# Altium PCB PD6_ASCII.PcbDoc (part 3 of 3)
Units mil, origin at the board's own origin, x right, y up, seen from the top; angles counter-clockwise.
Board outline 8543.31 x 5314.96 mil, 4 copper layers (Top Layer, VBAT Plane, GND Plane, Bottom Layer), stack 62.8 mil thick; 258 components, 142 nets, 690 pads, 87 vias.
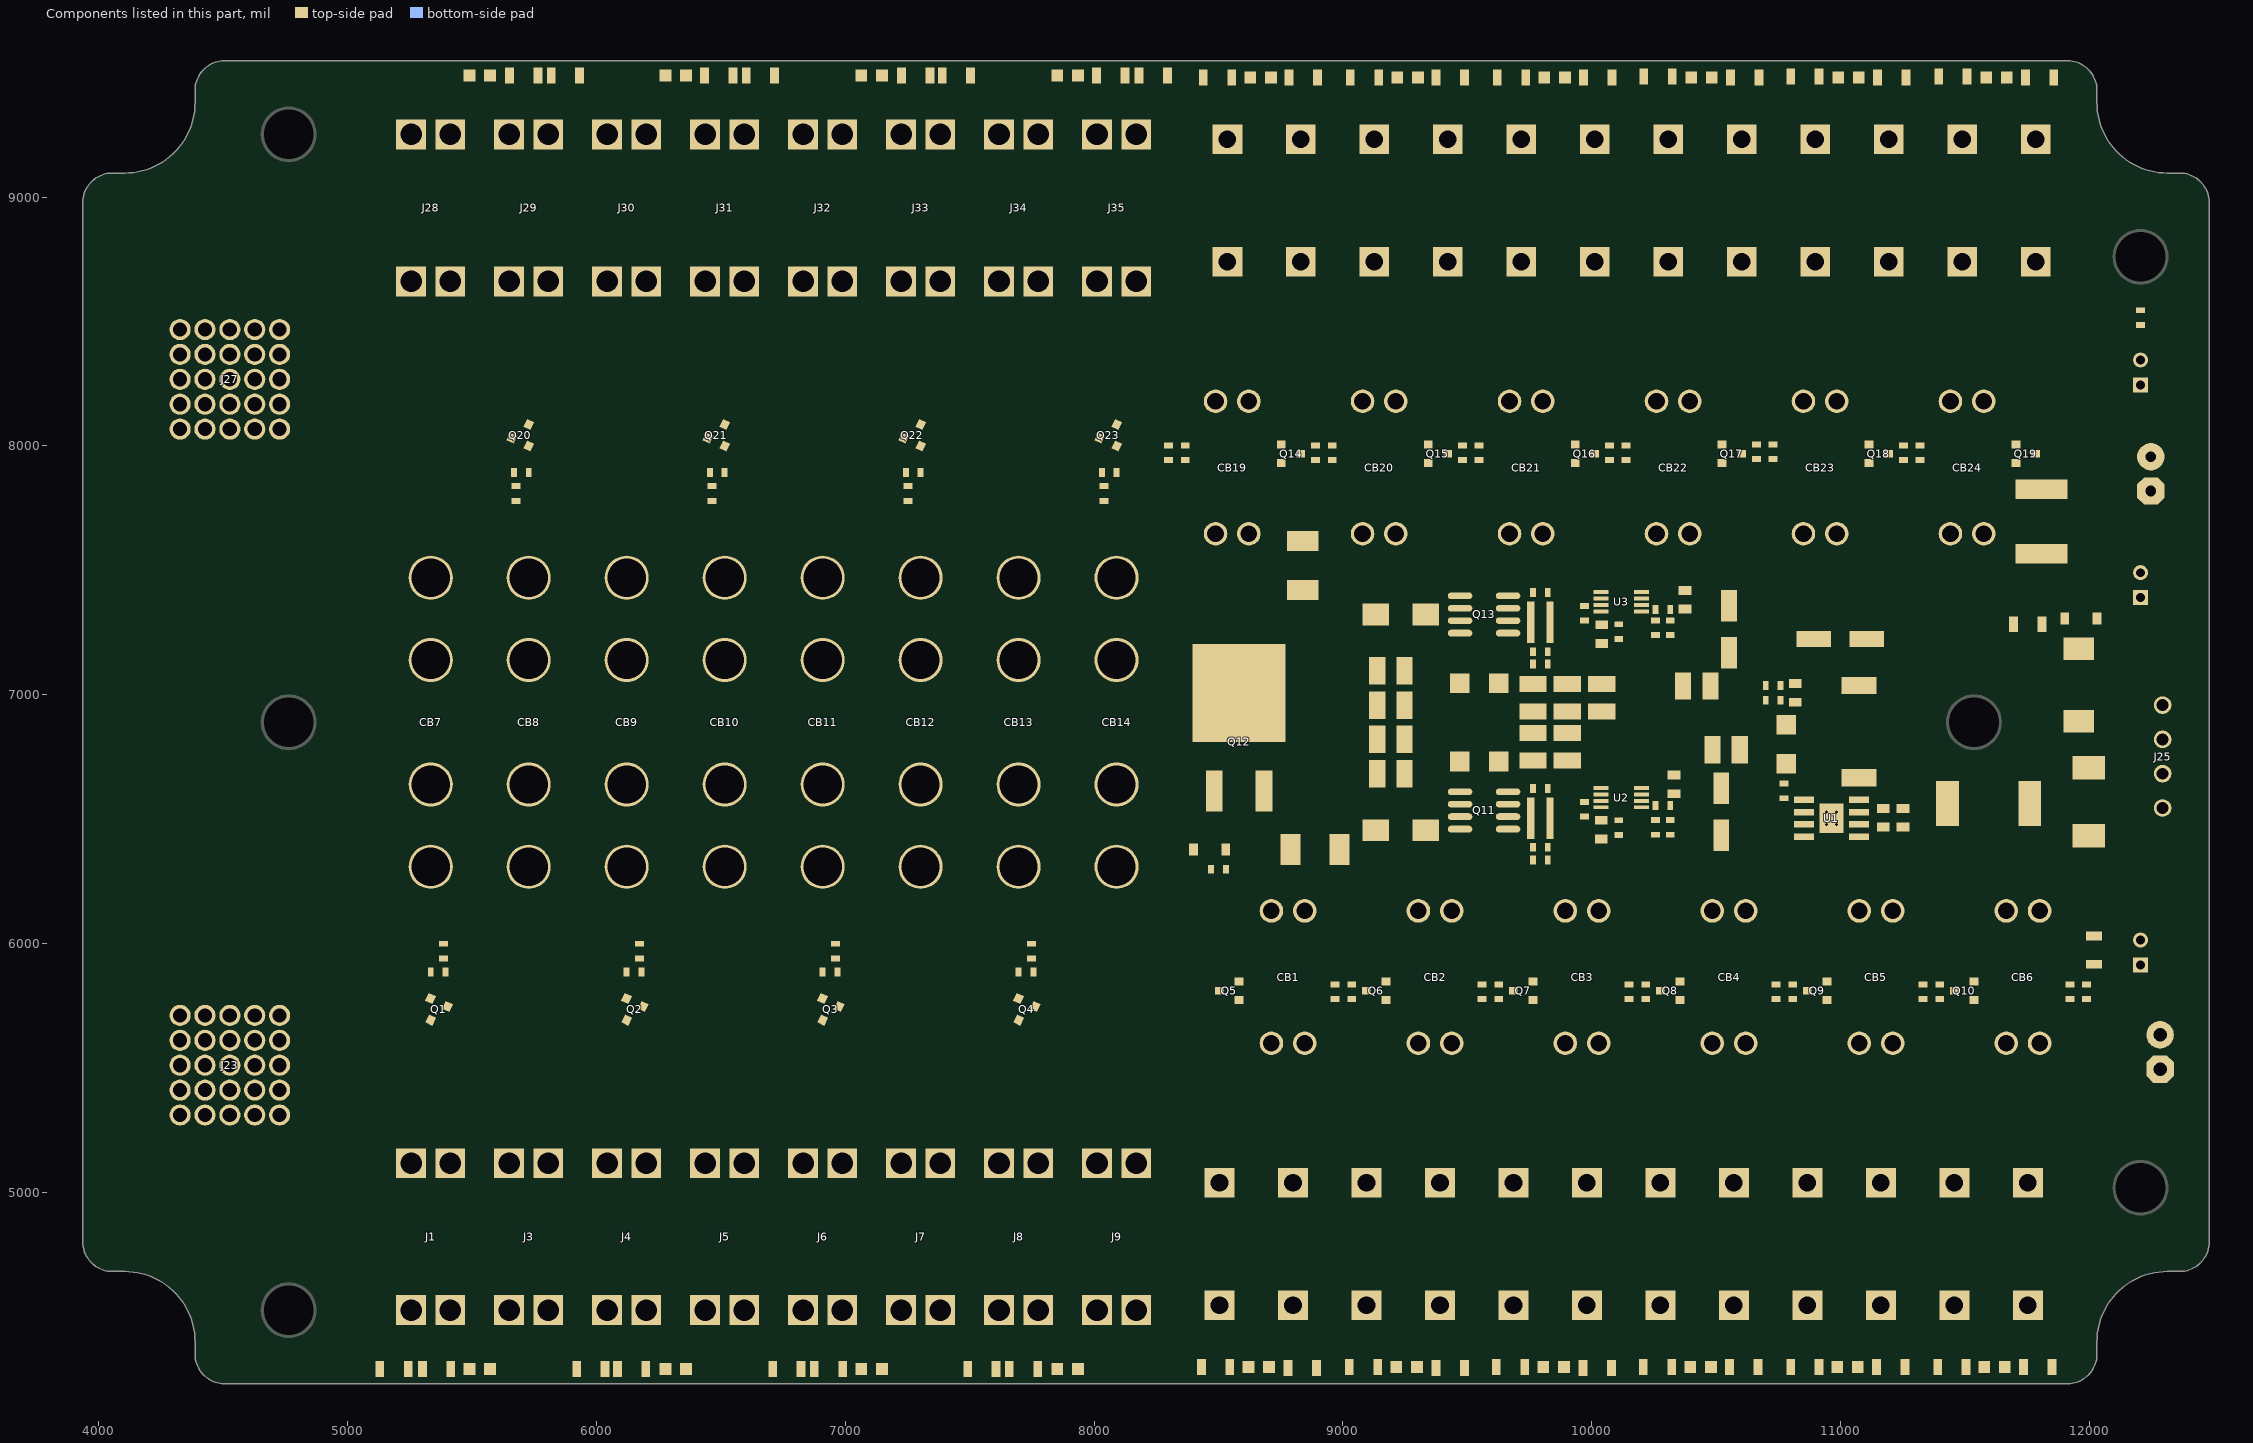
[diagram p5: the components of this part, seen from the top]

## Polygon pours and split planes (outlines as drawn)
VBAT on Top Layer "Top Layer-No Net" (solid, remove dead copper, pour order 1008): 8582.68,6259.84 11929.13,6259.84 11929.13,5870.08 8582.68,5870.08
VBAT on Top Layer "Top Layer-VBAT 1" (solid, remove dead copper, pour order 1007): 8257.87,7519.69 11669.29,7519.69 11669.29,7909.45 8257.87,7909.45 8257.87,7519.69
HIGHCURRENTOUT_3_2 on Top Layer "Top Layer-VBAT" (solid, remove dead copper, pour order 1020): 6338.58,7480.31 6338.58,7047.24 6299.21,7007.87 5944.88,7007.87 5905.51,7047.24 5905.51,7480.31 5748.03,7637.8 5748.03,8425.2 5905.51,8582.68 5905.51,9370.08 5944.88,9409.45 6299.21,9409.45 6338.58,9370.08 6338.58,8582.68 6496.06,8425.2 6496.06,7637.8
HIGHCURRENTOUT_2_2 on Top Layer "Top Layer-VBAT" (solid, remove dead copper, pour order 1019): 7125.98,7480.31 7125.98,7047.24 7086.61,7007.87 6732.28,7007.87 6692.91,7047.24 6692.91,7480.31 6535.43,7637.8 6535.43,8425.2 6692.91,8582.68 6692.91,9370.08 6732.28,9409.45 7086.61,9409.45 7125.98,9370.08 7125.98,8582.68 7283.46,8425.2 7283.46,7637.8
HIGHCURRENTOUT_1_2 on Top Layer "Top Layer-VBAT" (solid, remove dead copper, pour order 1018): 7913.39,7480.31 7913.39,7047.24 7874.02,7007.87 7519.69,7007.87 7480.31,7047.24 7480.31,7480.31 7322.83,7637.8 7322.83,8425.2 7480.31,8582.68 7480.31,9370.08 7519.69,9409.45 7874.02,9409.45 7913.39,9370.08 7913.39,8582.68 8070.87,8425.2 8070.87,7637.8
HIGHCURRENTOUT_4_2 on Top Layer "Top Layer-VBAT" (solid, remove dead copper, pour order 1014): 5551.18,7480.31 5551.18,7047.24 5511.81,7007.87 5157.48,7007.87 5118.11,7047.24 5118.11,7480.31 5039.37,7559.06 5039.37,8503.94 5118.11,8582.68 5118.11,9370.08 5157.48,9409.45 5511.81,9409.45 5551.18,9370.08 5551.18,8582.68 5708.66,8425.2 5708.66,7637.8
NetC3_2 on Top Layer "Top Layer-GND" (solid, remove dead copper, pour order 1000): 9566.93,6299.21 9734.25,6299.21 9734.25,6427.17 9812.99,6427.17 9812.99,6594.49 9606.3,6594.49 9566.93,6594.49
NetC19_2 on Top Layer "Top Layer-GND" (solid, remove dead copper, pour order 1002): 9566.93,7086.61 9734.25,7086.61 9734.25,7214.57 9812.99,7214.57 9812.99,7381.89 9606.3,7381.89 9566.93,7381.89
24_VIN on Top Layer "Top Layer-GND" (solid, remove dead copper, pour order 1001): 8858.27,7480.31 8858.27,6999.61 ccw(c8958.27,6999.61) 8958.27,6899.61 9183.07,6899.61 9183.07,7480.31
12_VIN on Top Layer "Top Layer-GND" (solid, remove dead copper, pour order 1003): 8858.27,6299.21 8858.27,6779.92 cw(c8958.27,6779.92) 8958.27,6879.92 9183.07,6879.92 9183.07,6299.21
HIGHCURRENTOUT_1_1 on Top Layer "Top Layer-VBAT" (solid, remove dead copper, pour order 1022): 5511.81,6299.21 5511.81,6732.28 5551.18,6771.65 5905.51,6771.65 5944.88,6732.28 5944.88,6299.21 6102.36,6141.73 6102.36,5354.33 5944.88,5196.85 5944.88,4409.45 5905.51,4370.08 5551.18,4370.08 5511.81,4409.45 5511.81,5196.85 5354.33,5354.33 5354.33,6141.73
HIGHCURRENTOUT_2_1 on Top Layer "Top Layer-VBAT" (solid, remove dead copper, pour order 1009): 6299.21,6299.21 6299.21,6732.28 6338.58,6771.65 6692.91,6771.65 6732.28,6732.28 6732.28,6299.21 6889.76,6141.73 6889.76,5354.33 6732.28,5196.85 6732.28,4409.45 6692.91,4370.08 6338.58,4370.08 6299.21,4409.45 6299.21,5196.85 6141.73,5354.33 6141.73,6141.73
HIGHCURRENTOUT_3_1 on Top Layer "Top Layer-VBAT" (solid, remove dead copper, pour order 1010): 7086.61,6299.21 7086.61,6732.28 7125.98,6771.65 7480.31,6771.65 7519.69,6732.28 7519.69,6299.21 7677.17,6141.73 7677.17,5354.33 7519.69,5196.85 7519.69,4409.45 7480.31,4370.08 7125.98,4370.08 7086.61,4409.45 7086.61,5196.85 6929.13,5354.33 6929.13,6141.73
HIGHCURRENTOUT_4_1 on Top Layer "Top Layer-VBAT" (solid, remove dead copper, pour order 1012): 7874.02,6299.21 7874.02,6732.28 7913.39,6771.65 8267.72,6771.65 8307.09,6732.28 8307.09,6299.21 8464.57,6141.73 8464.57,5354.33 8307.09,5196.85 8307.09,4409.45 8267.72,4370.08 7913.39,4370.08 7874.02,4409.45 7874.02,5196.85 7716.54,5354.33 7716.54,6141.73
VBAT on Top Layer "Top Layer-VBAT HP" (solid, remove dead copper, pour order 1023): 3838.58,7677.17 7913.39,7677.17 7913.39,7913.39 8257.87,7913.39 8257.87,6102.36 5511.81,6102.36 5511.81,4409.45 5000,4409.45 5000,4133.86 3838.58,4133.86
HIGHCURRENTOUT_2_1 on Bottom Layer "Top Layer-VBAT" (solid, remove dead copper, pour order 1004): 6299.21,6299.21 6299.21,6732.28 6338.58,6771.65 6692.91,6771.65 6732.28,6732.28 6732.28,6299.21 6889.76,6141.73 6889.76,5354.33 6732.28,5196.85 6732.28,5039.37 6692.91,5000 6338.58,5000 6299.21,5039.37 6299.21,5196.85 6141.73,5354.33 6141.73,6141.73
HIGHCURRENTOUT_3_1 on Bottom Layer "Top Layer-VBAT" (solid, remove dead copper, pour order 1006): 7086.61,6299.21 7086.61,6732.28 7125.98,6771.65 7480.31,6771.65 7519.69,6732.28 7519.69,6299.21 7677.17,6141.73 7677.17,5354.33 7519.69,5196.85 7519.69,5039.37 7480.31,5000 7125.98,5000 7086.61,5039.37 7086.61,5196.85 6929.13,5354.33 6929.13,6141.73
HIGHCURRENTOUT_4_1 on Bottom Layer "Top Layer-VBAT" (solid, remove dead copper, pour order 1011): 7874.02,6299.21 7874.02,6732.28 7913.39,6771.65 8267.72,6771.65 8307.09,6732.28 8307.09,6299.21 8464.57,6141.73 8464.57,5354.33 8307.09,5196.85 8307.09,5039.37 8267.72,5000 7913.39,5000 7874.02,5039.37 7874.02,5196.85 7716.54,5354.33 7716.54,6141.73
HIGHCURRENTOUT_4_2 on Bottom Layer "Top Layer-VBAT" (solid, remove dead copper, pour order 1013): 5551.18,7480.31 5551.18,7047.24 5511.81,7007.87 5157.48,7007.87 5118.11,7047.24 5118.11,7480.31 5039.37,7559.06 5039.37,8503.94 5118.11,8582.68 5118.11,8740.16 5157.48,8779.53 5511.81,8779.53 5551.18,8740.16 5551.18,8582.68 5708.66,8425.2 5708.66,7637.8
HIGHCURRENTOUT_3_2 on Bottom Layer "Top Layer-VBAT" (solid, remove dead copper, pour order 1015): 6338.58,7480.31 6338.58,7047.24 6299.21,7007.87 5944.88,7007.87 5905.51,7047.24 5905.51,7480.31 5748.03,7637.8 5748.03,8425.2 5905.51,8582.68 5905.51,8740.16 5944.88,8779.53 6299.21,8779.53 6338.58,8740.16 6338.58,8582.68 6496.06,8425.2 6496.06,7637.8
HIGHCURRENTOUT_2_2 on Bottom Layer "Top Layer-VBAT" (solid, remove dead copper, pour order 1016): 7125.98,7480.31 7125.98,7047.24 7086.61,7007.87 6732.28,7007.87 6692.91,7047.24 6692.91,7480.31 6535.43,7637.8 6535.43,8425.2 6692.91,8582.68 6692.91,8740.16 6732.28,8779.53 7086.61,8779.53 7125.98,8740.16 7125.98,8582.68 7283.46,8425.2 7283.46,7637.8
HIGHCURRENTOUT_1_2 on Bottom Layer "Top Layer-VBAT" (solid, remove dead copper, pour order 1017): 7913.39,7480.31 7913.39,7047.24 7874.02,7007.87 7519.69,7007.87 7480.31,7047.24 7480.31,7480.31 7322.83,7637.8 7322.83,8425.2 7480.31,8582.68 7480.31,8740.16 7519.69,8779.53 7874.02,8779.53 7913.39,8740.16 7913.39,8582.68 8070.87,8425.2 8070.87,7637.8
HIGHCURRENTOUT_1_1 on Bottom Layer "Top Layer-VBAT" (solid, remove dead copper, pour order 1021): 5511.81,6299.21 5511.81,6732.28 5551.18,6771.65 5905.51,6771.65 5944.88,6732.28 5944.88,6299.21 6102.36,6141.73 6102.36,5354.33 5944.88,5196.85 5944.88,5039.37 5905.51,5000 5551.18,5000 5511.81,5039.37 5511.81,5196.85 5354.33,5354.33 5354.33,6141.73
PSGND on Bottom Layer "PSGND-Bottom Layer" (solid, remove dead copper, pour order 1005): 8661.42,6299.21 8661.42,7047.24 8858.27,7244.09 8858.27,7480.31 12362.2,7480.31 12362.2,6299.21
GND on Bottom Layer "Bottom Layer-GND HP" (solid, remove dead copper, pour order 1021): 3897.64,9409.45 11929.13,9409.45 11929.13,4409.45 3897.64,4409.45
VBAT on VBAT Plane (split plane): 311 vertices, not listed, extent 3962.04,4257.32 12455.28,9522.21
GND on VBAT Plane (split plane): 4866.82,7928.46 4188.3,7928.46 4188.3,8606.97 4866.82,8606.97
GND on GND Plane (split plane): 311 vertices, not listed, extent 3962.04,4257.32 12455.28,9522.21
VBAT on GND Plane (split plane): 4866.82,5172.55 4188.3,5172.55 4188.3,5851.07 4866.82,5851.07

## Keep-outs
Keep-Out Layer:
  lines w6.89: 3937.01,4801.18 ccw(c4055.12,4801.18) 4055.12,4683.07 4104.33,4683.07 cw(c4104.33,4399.61) 4387.8,4399.61 4387.8,4350.39 ccw(c4505.91,4350.39) 4505.91,4232.28 11911.42,4232.28 ccw(c11911.42,4350.39) 12029.53,4350.39 12029.53,4399.61 cw(c12312.99,4399.61) 12312.99,4683.07 12362.2,4683.07 ccw(c12362.2,4801.18) 12480.31,4801.18 12480.31,8978.35 ccw(c12362.2,8978.35) 12362.2,9096.46 12312.99,9096.46 cw(c12312.99,9379.92) 12029.53,9379.92 12029.53,9429.13 ccw(c11911.42,9429.13) 11911.42,9547.24 4505.91,9547.24 ccw(c4505.91,9429.13) 4387.8,9429.13 4387.8,9379.92 cw(c4104.33,9379.92) 4104.33,9096.46 4055.12,9096.46 ccw(c4055.12,8978.35) 3937.01,8978.35 3937.01,6889.76 3937.01,4801.18

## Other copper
Top Layer:
  rectangle net VBAT: 8582.68,6305.12 8801.18,6452.76
  rectangle net PSGND: 8582.68,6466.54 8838.58,6732.28
  rectangle net PSGND: 9818.9,7208.66 9925.2,7374.02
  rectangle net PSGND: 9818.9,6421.26 9925.2,6586.61
  rectangle net LOWCURRENTOUT_6_1: 11555.12,4370.08 11948.82,5748.03
  rectangle net LOWCURRENTOUT_5_1: 10964.57,4370.08 11358.27,5748.03
  region net LOWCURRENTOUT_6_1: 12027.56,5748.03 11476.38,5748.03 11476.38,5137.8 12027.56,5137.8
  region net LOWCURRENTOUT_5_1: 11437.01,5748.03 10885.83,5748.03 10885.83,5137.8 11437.01,5137.8
  rectangle net LOWCURRENTOUT_1_1: 8602.36,4370.08 8996.06,5748.03
  rectangle net LOWCURRENTOUT_2_1: 9192.91,4370.08 9586.61,5748.03
  rectangle net LOWCURRENTOUT_3_1: 9783.46,4370.08 10177.17,5748.03
  rectangle net LOWCURRENTOUT_4_1: 10374.02,4370.08 10767.72,5748.03
  region net LOWCURRENTOUT_1_1: 9074.8,5748.03 8523.62,5748.03 8523.62,5137.8 9074.8,5137.8
  region net LOWCURRENTOUT_2_1: 9665.35,5748.03 9114.17,5748.03 9114.17,5137.8 9665.35,5137.8
  region net LOWCURRENTOUT_3_1: 10255.91,5748.03 9704.72,5748.03 9704.72,5137.8 10255.91,5137.8
  region net LOWCURRENTOUT_4_1: 10846.46,5748.03 10295.28,5748.03 10295.28,5137.8 10846.46,5137.8
  rectangle net GND: 4173.23,7913.39 4881.89,8622.05
  region net LOWCURRENTOUT_6_2: 8732.28,9409.45 8338.58,9409.45 8338.58,8031.5 8732.28,8031.5
  rectangle net LOWCURRENTOUT_6_2: 8259.84,8031.5 8811.02,8641.73
  region net LOWCURRENTOUT_5_2: 9322.83,9409.45 8929.13,9409.45 8929.13,8031.5 9322.83,8031.5
  rectangle net LOWCURRENTOUT_5_2: 8850.39,8031.5 9401.57,8641.73
  region net LOWCURRENTOUT_4_2: 9913.39,9409.45 9519.69,9409.45 9519.69,8031.5 9913.39,8031.5
  rectangle net LOWCURRENTOUT_4_2: 9440.94,8031.5 9992.13,8641.73
  region net LOWCURRENTOUT_3_2: 10503.94,9409.45 10110.24,9409.45 10110.24,8031.5 10503.94,8031.5
  rectangle net LOWCURRENTOUT_3_2: 10031.5,8031.5 10582.68,8641.73
  region net LOWCURRENTOUT_2_2: 11094.49,9409.45 10700.79,9409.45 10700.79,8031.5 11094.49,8031.5
  rectangle net LOWCURRENTOUT_2_2: 10622.05,8031.5 11173.23,8641.73
  region net LOWCURRENTOUT_1_2: 11685.04,9409.45 11291.34,9409.45 11291.34,8031.5 11685.04,8031.5
  rectangle net LOWCURRENTOUT_1_2: 11212.6,8031.5 11763.78,8641.73
Bottom Layer:
  rectangle net LOWCURRENTOUT_6_1: 11555.12,4921.26 11948.82,5748.03
  rectangle net LOWCURRENTOUT_5_1: 10964.57,4921.26 11358.27,5748.03
  rectangle net LOWCURRENTOUT_1_1: 8602.36,4921.26 8996.06,5748.03
  rectangle net LOWCURRENTOUT_2_1: 9192.91,4921.26 9586.61,5748.03
  rectangle net LOWCURRENTOUT_3_1: 9783.46,4921.26 10177.17,5748.03
  rectangle net LOWCURRENTOUT_4_1: 10374.02,4921.26 10767.72,5748.03
  rectangle net VBAT: 4173.23,5157.48 4881.89,5866.14
  region net LOWCURRENTOUT_6_2: 8732.28,8858.27 8338.58,8858.27 8338.58,8031.5 8732.28,8031.5
  region net LOWCURRENTOUT_5_2: 9322.83,8858.27 8929.13,8858.27 8929.13,8031.5 9322.83,8031.5
  region net LOWCURRENTOUT_4_2: 9913.39,8858.27 9519.69,8858.27 9519.69,8031.5 9913.39,8031.5
  region net LOWCURRENTOUT_3_2: 10503.94,8858.27 10110.24,8858.27 10110.24,8031.5 10503.94,8031.5
  region net LOWCURRENTOUT_2_2: 11094.49,8858.27 10700.79,8858.27 10700.79,8031.5 11094.49,8031.5
  region net LOWCURRENTOUT_1_2: 11685.04,8858.27 11291.34,8858.27 11291.34,8031.5 11685.04,8031.5
VBAT Plane (plane layer: these items are gaps in the copper):
  lines w30: 4173.23,7913.39 4881.89,7913.39 4881.89,8622.05 4173.23,8622.05 4173.23,7913.39
  lines w50: 12480.31,4801.18 cw(c12362.2,4801.18) 12362.2,4683.07 12312.99,4683.07 ccw(c12312.99,4399.61) 12029.53,4399.61 12029.53,4350.39 cw(c11911.42,4350.39) 11911.42,4232.28 4505.91,4232.28 cw(c4505.91,4350.39) 4387.8,4350.39 4387.8,4399.61 ccw(c4104.33,4399.61) 4104.33,4683.07 4055.12,4683.07 cw(c4055.12,4801.18) 3937.01,4801.18 3937.01,8978.35 cw(c4055.12,8978.35) 4055.12,9096.46 4104.33,9096.46 ccw(c4104.33,9379.92) 4387.8,9379.92 4387.8,9429.13 cw(c4505.91,9429.13) 4505.91,9547.24 11911.42,9547.24 cw(c11911.42,9429.13) 12029.53,9429.13 12029.53,9379.92 ccw(c12312.99,9379.92) 12312.99,9096.46 12362.2,9096.46 cw(c12362.2,8978.35) 12480.31,8978.35 ; 12480.31,4801.18 12480.31,8978.35 ; 12480.31,4801.18 12480.31,4801.18 ; 12480.31,8978.35 12480.31,8978.35
GND Plane (plane layer: these items are gaps in the copper):
  lines w30: 4173.23,5157.48 4173.23,5866.14 4881.89,5866.14 4881.89,5157.48 4173.23,5157.48
  lines w50: 12480.31,4801.18 cw(c12362.2,4801.18) 12362.2,4683.07 12312.99,4683.07 ccw(c12312.99,4399.61) 12029.53,4399.61 12029.53,4350.39 cw(c11911.42,4350.39) 11911.42,4232.28 4505.91,4232.28 cw(c4505.91,4350.39) 4387.8,4350.39 4387.8,4399.61 ccw(c4104.33,4399.61) 4104.33,4683.07 4055.12,4683.07 cw(c4055.12,4801.18) 3937.01,4801.18 3937.01,8978.35 cw(c4055.12,8978.35) 4055.12,9096.46 4104.33,9096.46 ccw(c4104.33,9379.92) 4387.8,9379.92 4387.8,9429.13 cw(c4505.91,9429.13) 4505.91,9547.24 11911.42,9547.24 cw(c11911.42,9429.13) 12029.53,9429.13 12029.53,9379.92 ccw(c12312.99,9379.92) 12312.99,9096.46 12362.2,9096.46 cw(c12362.2,8978.35) 12480.31,8978.35 ; 12480.31,4801.18 12480.31,8978.35 ; 12480.31,4801.18 12480.31,4801.18 ; 12480.31,8978.35 12480.31,8978.35

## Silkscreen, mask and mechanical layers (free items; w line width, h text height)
Top Overlay:
  lines w8: 5147.64,9478.35 5354.33,9478.35 ; 5324.8,9458.66 5354.33,9478.35 ; 5324.8,9498.03 5354.33,9478.35 ; 9035.43,6643.7 9074.8,6643.7 ; 9035.43,6663.39 9074.8,6663.39 ; 9035.43,6683.07 9074.8,6683.07 ; 9035.43,6702.76 9074.8,6702.76 ; 9035.43,6722.44 9074.8,6722.44 ; 9035.43,6781.5 9074.8,6781.5 ; 9035.43,6801.18 9074.8,6801.18 ; 9035.43,6820.87 9074.8,6820.87 ; 9035.43,6840.55 9074.8,6840.55 ; 9035.43,6860.24 9074.8,6860.24 ; 9035.43,6919.29 9074.8,6919.29 ; 9035.43,6938.98 9074.8,6938.98 ; 9035.43,6958.66 9074.8,6958.66 ; 9035.43,6978.35 9074.8,6978.35 ; 9035.43,6998.03 9074.8,6998.03 ; 9035.43,7057.09 9074.8,7057.09 ; 9035.43,7076.77 9074.8,7076.77 ; 9035.43,7096.46 9074.8,7096.46 ; 9035.43,7116.14 9074.8,7116.14 ; 9035.43,7135.83 9074.8,7135.83 ; 9980.32,7391.73 9990.16,7431.1
  lines w10: 10259.84,7433.07 10259.84,7393.7 10275.59,7377.95 ; 10342.52,6551.18 10362.2,6531.5 10362.2,6413.39
  text "D18-27" at 4881.89,9458.66 h45
  text "R62-81" at 4881.89,9399.61 h45
  text "VBATT-" at 4940.94,8503.94 h80 r270
  text "Rev 6" at 4242.13,7795.28 h80 r270
  text "Power Distribution Panel" at 4370.08,7795.28 h80 r270
  text "VBATT+" at 4940.94,5748.03 h80 r270
  text "EJVW" at 5511.81,5748.03 h50
  text "D1-10" at 4842.52,4350.39 h45
  text "R1-20" at 4842.52,4291.34 h45
Mechanical 1:
  lines w6.89: 3937.01,4801.18 ccw(c4055.12,4801.18) 4055.12,4683.07 4104.33,4683.07 cw(c4104.33,4399.61) 4387.8,4399.61 4387.8,4350.39 ccw(c4505.91,4350.39) 4505.91,4232.28 11911.42,4232.28 ccw(c11911.42,4350.39) 12029.53,4350.39 12029.53,4399.61 cw(c12312.99,4399.61) 12312.99,4683.07 12362.2,4683.07 ccw(c12362.2,4801.18) 12480.31,4801.18 12480.31,8978.35 ccw(c12362.2,8978.35) 12362.2,9096.46 12312.99,9096.46 cw(c12312.99,9379.92) 12029.53,9379.92 12029.53,9429.13 ccw(c11911.42,9429.13) 11911.42,9547.24 4505.91,9547.24 ccw(c4505.91,9429.13) 4387.8,9429.13 4387.8,9379.92 cw(c4104.33,9379.92) 4104.33,9096.46 4055.12,9096.46 ccw(c4055.12,8978.35) 3937.01,8978.35 3937.01,6889.76 3937.01,4801.18
  lines w39.37: 16633.86,8070.87 16240.16,7283.46 17027.56,7775.59 ; 16633.86,10037.8 cw(c16733.86,10037.8) 16733.86,10137.8 19978.74,10137.8 cw(c19978.74,10037.8) 20078.74,10037.8 ; 16633.86,10039.37 16633.86,7875.59 ccw(c16733.86,7875.59) 16733.86,7775.59 19978.74,7775.59 ccw(c19978.74,7875.59) 20078.74,7875.59 20078.74,10039.37
  text "ATTENTION EARTHLINGS" at 17125.98,9842.52 h118.11
  text "CALIBRATE BLASTERS THUSLY" at 16929.13,7874.02 h118.11
Mechanical 13:
  lines w10: 8169.29,6889.76 8248.03,6889.76 ; 8208.66,6850.39 8208.66,6929.13
Drill Drawing:
  text "All Drill Dimensions are Finished Hole Size" at 17125.98,9724.41 h50
  text "STACKUP" at 14901.57,8622.05 h50
  text "1 oz Cu" at 14901.57,8543.31 h50
  text "3 oz Cu" at 14901.57,8385.83 h50
  text "3 oz Cu" at 14901.57,8228.35 h50
  text "1 oz Cu" at 14901.57,8070.87 h50
  text ".Legend" at 16929.13,8070.87 h50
